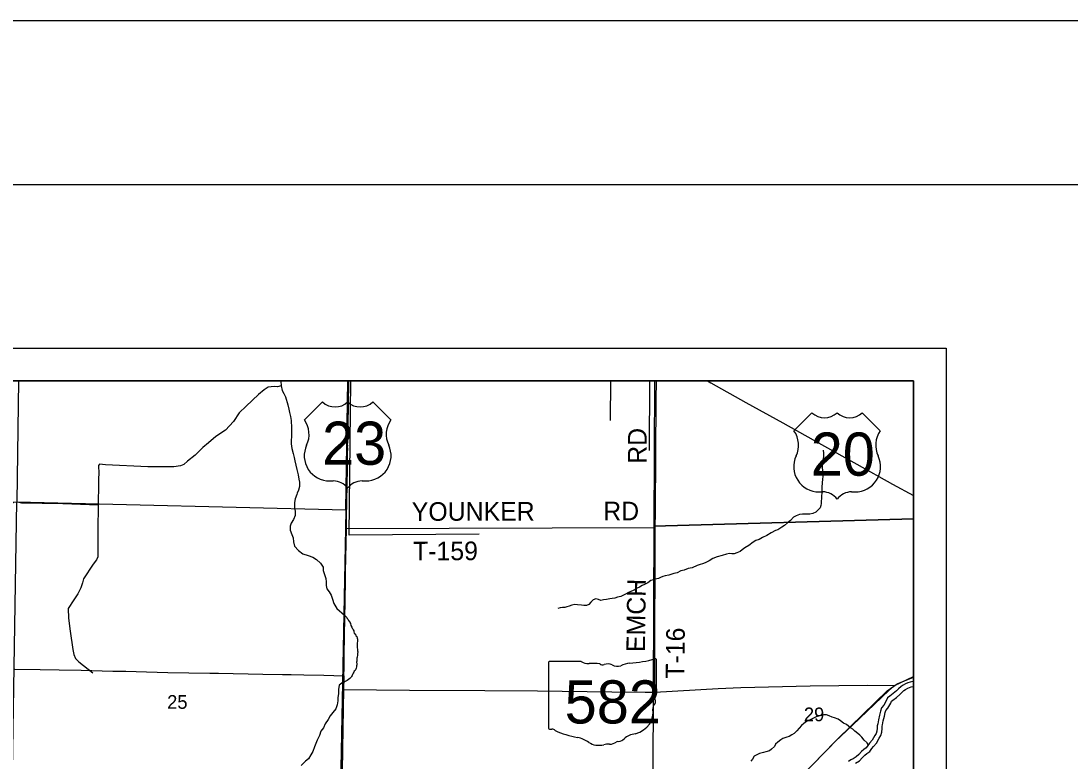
# Model space of a CAD drawing. Extents: x 0 to 34, y 0 to 22.
# Drawn here: x 6.172 to 9.379, y 19.739 to 22 of the extents above; entities that cross this region are included whole.
import ezdxf

# ---------------------------------------------------------------- set-up
doc = ezdxf.new("R2010")
doc.units = 0
for name, color, linetype in [('Default', 7, 'Continuous'), ('GM_X_Major_River', 7, 'Continuous'), ('GM_X_Minor_River', 7, 'Continuous'), ('GM_X_Rail_Line', 7, 'Continuous'), ('GM_X_Section', 7, 'Continuous'), ('GM_X_Section_Text', 7, 'Continuous'), ('GM_X_State_Location', 7, 'Continuous'), ('GM_X_State_Route', 7, 'Continuous'), ('GM_X_State_Shield', 7, 'Continuous'), ('GM_X_Township_Road', 7, 'Continuous'), ('GM_X_Township_Road_Text', 7, 'Continuous'), ('GM_X_US_Location', 7, 'Continuous'), ('GM_X_US_Route', 7, 'Continuous'), ('GM_X_US_Shield', 7, 'Continuous'), ('SH_Border', 7, 'Continuous'), ('SH_Cut_Line', 7, 'Continuous'), ('SH_Data', 7, 'Continuous')]:
    doc.layers.add(name, color=color, linetype=linetype)

msp = doc.modelspace()

# ---------------------------------------------------------------- linework, layer by layer
at = {"layer": 'Default'}
for points in [[(7.1537, 19.7074), (7.1558, 19.838), (7.1582, 19.9576), (7.1584, 19.9701), (7.1585, 19.983), (7.1586, 19.9996), (7.1589, 20.0234), (7.1593, 20.0575), (7.1605, 20.1258), (7.1613, 20.1709), (7.1624, 20.2315), (7.1626, 20.2502), (7.1628, 20.2688), (7.1637, 20.317), (7.1651, 20.4024), (7.1662, 20.449), (7.1662, 20.4497), (7.1667, 20.4801), (7.1675, 20.5329), (7.1683, 20.5811), (7.1691, 20.6324), (7.1697, 20.665), (7.1697, 20.679), (7.1699, 20.6945), (7.1698, 20.6976), (7.1699, 20.7023), (7.1698, 20.7054), (7.1699, 20.7132), (7.1711, 20.766), (7.1724, 20.8281), (7.1733, 20.8949), (7.1734, 20.9), (3.1549, 20.9)], [(8.9, 16.9874), (8.9, 20.9), (7.1734, 20.9), (7.1733, 20.8949), (7.1724, 20.8281), (7.1711, 20.766), (7.1699, 20.7132), (7.1698, 20.7054), (7.1699, 20.7023), (7.1698, 20.6976), (7.1699, 20.6945), (7.1697, 20.679), (7.1697, 20.665), (7.1691, 20.6324), (7.1683, 20.5811), (7.1675, 20.5329), (7.1667, 20.4801), (7.1662, 20.4497), (7.1662, 20.449), (7.1651, 20.4024), (7.1637, 20.317), (7.1628, 20.2688), (7.1626, 20.2502), (7.1624, 20.2315), (7.1613, 20.1709), (7.1605, 20.1258), (7.1593, 20.0575), (7.1589, 20.0234), (7.1586, 19.9996), (7.1585, 19.983), (7.1584, 19.9701), (7.1582, 19.9576), (7.1558, 19.838), (7.1537, 19.7074)]]:
    msp.add_lwpolyline(points, dxfattribs=at)
for points in [[(7.1717, 20.9), (6.1646, 20.9), (6.1602, 20.5302), (7.1654, 20.5062)], [(8.9, 20.4788), (8.9, 20.9), (8.1091, 20.9), (8.1063, 20.4559)], [(8.9, 19.4792), (8.9, 20.4788), (8.1063, 20.4559), (8.1023, 19.4482)]]:
    msp.add_lwpolyline(points, close=True, dxfattribs=at)
at = {"layer": 'GM_X_Major_River'}
for points in [[(8.9, 19.9817), (8.8977, 19.9814), (8.8901, 19.9798), (8.8829, 19.9779), (8.8753, 19.974), (8.8685, 19.9702), (8.8621, 19.9664), (8.8541, 19.9591), (8.8481, 19.9526), (8.8386, 19.945), (8.8277, 19.9366), (8.8212, 19.9312), (8.8171, 19.9225), (8.8092, 19.9088), (8.8024, 19.9008), (8.7994, 19.8913), (8.7964, 19.8787), (8.793, 19.8647), (8.7908, 19.8525), (8.7893, 19.846), (8.7897, 19.8384), (8.7882, 19.8297), (8.7863, 19.8225), (8.7822, 19.816), (8.7743, 19.8023), (8.766, 19.7928), (8.7603, 19.7855), (8.7558, 19.7787), (8.7486, 19.7733), (8.741, 19.7672), (8.7327, 19.7584), (8.7255, 19.7512), (8.7157, 19.7454), (8.7092, 19.742), (8.7013, 19.7366)], [(8.7231, 19.7322), (8.7349, 19.7391), (8.7436, 19.7479), (8.7513, 19.756), (8.7579, 19.7613), (8.767, 19.7681), (8.7726, 19.7767), (8.7777, 19.7831), (8.7867, 19.7934), (8.7952, 19.8081), (8.8004, 19.8163), (8.8031, 19.8265), (8.8049, 19.8376), (8.8045, 19.8447), (8.8056, 19.8494), (8.8079, 19.8615), (8.8111, 19.8752), (8.814, 19.8872), (8.8159, 19.8933), (8.8216, 19.9), (8.8305, 19.9154), (8.8335, 19.9217), (8.8371, 19.9247), (8.848, 19.9331), (8.8584, 19.9415), (8.8648, 19.9483), (8.8712, 19.9541), (8.8761, 19.9571), (8.8825, 19.9607), (8.8884, 19.9636), (8.8936, 19.965), (8.9, 19.9664)]]:
    msp.add_lwpolyline(points, dxfattribs=at)
at = {"layer": 'GM_X_Minor_River'}
for p, q in [((7.1759, 20.4285), (7.1802, 20.9)), ((7.9745, 20.9), (7.9729, 20.7792)), ((8.093, 20.9), (8.0923, 20.6874)), ((7.1758, 20.4288), (7.1759, 20.4288)), ((7.5724, 20.432), (7.1759, 20.4285))]:
    msp.add_line(p, q, dxfattribs=at)
for points in [[(6.9678, 20.8853), (6.9564, 20.8821), (6.9458, 20.8828), (6.9276, 20.8805), (6.9153, 20.8729), (6.8983, 20.8581), (6.8603, 20.8233), (6.8389, 20.8022), (6.822, 20.7761), (6.7979, 20.7497), (6.7682, 20.7307), (6.7458, 20.7108), (6.7284, 20.6964), (6.7051, 20.6734), (6.6819, 20.655), (6.6699, 20.6447), (6.6596, 20.6407), (6.6394, 20.6374), (6.5599, 20.6378), (6.4313, 20.644), (6.4128, 20.646), (6.4096, 20.6415), (6.4102, 20.6168), (6.4098, 20.602), (6.4091, 20.5872), (6.4085, 20.5208), (6.4078, 20.4446), (6.4076, 20.374), (6.4076, 20.3626), (6.4029, 20.3529), (6.3934, 20.3398), (6.3632, 20.295), (6.3602, 20.2829), (6.3553, 20.2682), (6.3461, 20.2495), (6.3336, 20.2308), (6.317, 20.205), (6.3174, 20.175), (6.3225, 20.1355), (6.3313, 20.0795), (6.3336, 20.0642), (6.3386, 20.0523), (6.3493, 20.0414), (6.3924, 20.0085)], [(6.9666, 20.9), (6.9667, 20.8989), (6.9678, 20.8853), (6.9709, 20.8711), (6.9756, 20.8615), (6.9806, 20.8515), (6.9876, 20.8267), (6.9911, 20.8137), (6.9931, 20.8031), (6.9958, 20.7912), (6.9978, 20.779), (6.9995, 20.757), (6.9995, 20.7426), (6.9988, 20.7289), (6.9982, 20.7191), (6.9986, 20.7073), (7.0006, 20.6932), (7.004, 20.6783), (7.0078, 20.6657), (7.0095, 20.6562), (7.0129, 20.6424), (7.016, 20.6298), (7.0198, 20.613), (7.0221, 20.6001), (7.0238, 20.5905), (7.0238, 20.5776), (7.0205, 20.5667), (7.0161, 20.557)], [(8.6241, 20.6883), (8.6253, 20.6788), (8.6253, 20.6719), (8.6242, 20.6594), (8.6219, 20.6488), (8.6216, 20.6408), (8.6212, 20.6343), (8.622, 20.6271), (8.6228, 20.6195), (8.6229, 20.6093), (8.6225, 20.599), (8.6214, 20.5899), (8.6203, 20.5747), (8.62, 20.5656), (8.6196, 20.5561), (8.6193, 20.5497), (8.6189, 20.5421), (8.6182, 20.5318), (8.6182, 20.5254), (8.6175, 20.5189), (8.6149, 20.5121), (8.6081, 20.5052), (8.6013, 20.4991), (8.5929, 20.4945), (8.5838, 20.4929), (8.569, 20.4925), (8.5607, 20.4924), (8.552, 20.492), (8.5414, 20.4881), (8.5334, 20.4836), (8.5243, 20.4736), (8.5156, 20.4668), (8.5058, 20.458), (8.4978, 20.453), (8.4854, 20.4453), (8.4782, 20.443), (8.4653, 20.4361), (8.4516, 20.4277), (8.4388, 20.4212), (8.4282, 20.415), (8.4183, 20.4123), (8.4107, 20.4077), (8.3967, 20.3974), (8.3843, 20.3901), (8.3767, 20.3836), (8.3703, 20.3791), (8.3608, 20.3748), (8.3524, 20.3718), (8.3449, 20.3721), (8.3376, 20.3724), (8.3289, 20.3705), (8.3153, 20.3662), (8.2997, 20.3624), (8.2865, 20.3574), (8.2755, 20.3505), (8.2634, 20.3443), (8.2558, 20.3409), (8.2482, 20.3386), (8.2395, 20.3355), (8.224, 20.3289), (8.2118, 20.3266), (8.199, 20.322), (8.1887, 20.3193), (8.1777, 20.3139), (8.1679, 20.3112), (8.1588, 20.3089), (8.152, 20.3069), (8.1417, 20.3046), (8.1338, 20.3023), (8.1273, 20.2996), (8.1209, 20.2965), (8.111, 20.2938), (8.1042, 20.2919), (8.097, 20.2899), (8.0887, 20.2827), (8.0777, 20.2784), (8.0713, 20.2746), (8.0633, 20.27), (8.0561, 20.2666), (8.0466, 20.2604), (8.0387, 20.2577), (8.0296, 20.2531), (8.0205, 20.2482), (8.0141, 20.2455), (8.0054, 20.2412), (7.9959, 20.2389), (7.9875, 20.2362), (7.9796, 20.2354), (7.9724, 20.2346), (7.9621, 20.2323), (7.9527, 20.2311), (7.9447, 20.2292), (7.9379, 20.2325), (7.9291, 20.2344), (7.9208, 20.2309), (7.9144, 20.2237), (7.9076, 20.2172), (7.9004, 20.2137), (7.8928, 20.2133), (7.8856, 20.2148), (7.8734, 20.2155)], [(7.0161, 20.557), (7.0153, 20.5528), (7.0108, 20.5396), (7.0082, 20.5287), (7.0086, 20.5139), (7.0109, 20.5009), (7.0103, 20.4892), (7.005, 20.4768), (6.9987, 20.4655), (6.9954, 20.4557), (6.9951, 20.4436), (7.0001, 20.4306), (7.0044, 20.421), (7.0056, 20.4084), (7.0083, 20.3951), (7.0205, 20.3823), (7.0339, 20.3721), (7.05, 20.3664), (7.0643, 20.3611), (7.0758, 20.3544)], [(6.4085, 20.5208), (6.3, 20.5246), (6.1739, 20.5261), (6.1619, 20.5299), (6.1493, 20.5283), (6.142, 20.5235), (6.1391, 20.5122), (6.1372, 20.3437)], [(7.0758, 20.3544), (7.0877, 20.3427), (7.0957, 20.3307), (7.0962, 20.3209), (7.0997, 20.309), (7.1043, 20.2964), (7.1048, 20.2857), (7.1053, 20.2747), (7.1077, 20.2652), (7.1139, 20.2552), (7.1201, 20.2455), (7.1247, 20.2329), (7.1282, 20.2199), (7.1377, 20.2049), (7.1613, 20.1842)], [(7.8734, 20.2155), (7.8654, 20.2166), (7.8556, 20.2146), (7.8476, 20.2116), (7.8412, 20.2093), (7.8347, 20.2073), (7.8279, 20.2073), (7.8199, 20.2069), (7.8135, 20.2046)], [(7.1613, 20.1842), (7.1664, 20.1793), (7.1679, 20.1766), (7.1698, 20.1736), (7.172, 20.1709), (7.1735, 20.1682), (7.1761, 20.1655), (7.1779, 20.1621), (7.1794, 20.159), (7.1804, 20.1529), (7.1838, 20.1476), (7.1849, 20.1449), (7.1867, 20.1422), (7.1878, 20.1392), (7.1893, 20.1361), (7.1896, 20.1331), (7.1911, 20.1289), (7.1944, 20.1258), (7.1962, 20.1212), (7.1989, 20.1186), (7.1999, 20.1144), (7.2006, 20.1109), (7.2005, 20.1037), (7.2001, 20.1), (7.2, 20.092), (7.2003, 20.0893), (7.2002, 20.0855), (7.2013, 20.0798), (7.2012, 20.0749), (7.2016, 20.0719), (7.2011, 20.0673), (7.201, 20.0624), (7.2002, 20.0563), (7.1994, 20.0529), (7.1989, 20.0465), (7.1985, 20.0434), (7.1984, 20.0408), (7.1991, 20.0359), (7.1991, 20.0324), (7.1979, 20.029), (7.1975, 20.026), (7.197, 20.0222), (7.1958, 20.0192), (7.1935, 20.0154), (7.1912, 20.0128), (7.1893, 20.0098), (7.1881, 20.0068), (7.1858, 20.003), (7.1846, 20), (7.1831, 19.9972), (7.1821, 19.9951)], [(7.1575, 19.979), (7.1449, 19.97), (7.1432, 19.9569), (7.1425, 19.9437), (7.1411, 19.9327), (7.1409, 19.9228), (7.1387, 19.91), (7.1346, 19.8979), (7.1256, 19.8864), (7.1174, 19.8767), (7.1114, 19.8651), (7.1024, 19.852), (7.0968, 19.8404), (7.0893, 19.8296), (7.0852, 19.8164), (7.0777, 19.8025), (7.074, 19.792), (7.07, 19.7815), (7.0647, 19.7676), (7.058, 19.7579), (7.0513, 19.7451), (7.0416, 19.7385), (7.0284, 19.7252)], [(7.1821, 19.9951), (7.1778, 19.991), (7.1689, 19.9848), (7.1612, 19.9804), (7.1575, 19.979)], [(8.7614, 19.7869), (8.7588, 19.7943), (8.7496, 19.8022), (8.742, 19.8109), (8.7363, 19.8173), (8.7298, 19.8226), (8.7214, 19.8294), (8.715, 19.8358), (8.7081, 19.8399), (8.6952, 19.8501), (8.6864, 19.8538), (8.6769, 19.8618), (8.6697, 19.8667), (8.659, 19.8708), (8.6518, 19.8723), (8.6427, 19.8768), (8.634, 19.8794), (8.6264, 19.8793), (8.6192, 19.8774), (8.6124, 19.8762), (8.6025, 19.8731), (8.5927, 19.8685), (8.582, 19.8635), (8.5737, 19.8589), (8.565, 19.8536), (8.5578, 19.8471), (8.551, 19.8391), (8.5438, 19.8311), (8.5351, 19.8227), (8.528, 19.8185), (8.52, 19.8139), (8.5132, 19.8112), (8.5011, 19.8073), (8.4946, 19.8035), (8.4855, 19.7966), (8.4787, 19.7905), (8.4753, 19.7833), (8.4663, 19.7749), (8.4598, 19.7695), (8.4492, 19.7664), (8.442, 19.7641), (8.4295, 19.7614), (8.4129, 19.753), (8.4083, 19.7446), (8.4027, 19.7381)]]:
    msp.add_lwpolyline(points, dxfattribs=at)
at = {"layer": 'GM_X_Rail_Line'}
msp.add_lwpolyline([(7.1295, 18.535), (7.5214, 18.7256), (7.5415, 18.727), (7.7361, 18.8905), (7.8156, 18.9525), (8.1721, 19.3059), (8.3177, 19.4462), (8.6699, 19.8071), (8.8197, 19.9527), (8.8503, 19.9748), (8.9, 19.9949)], dxfattribs=at)
at = {"layer": 'GM_X_Section'}
msp.add_lwpolyline([(7.1654, 20.5062), (7.1646, 20.4494), (7.146, 19.507), (6.1433, 19.5215), (6.1602, 20.5302)], close=True, dxfattribs=at)
at = {"layer": 'GM_X_State_Route'}
for points in [[(6.1537, 20.0192), (6.2312, 20.0182), (6.289, 20.0171), (6.3561, 20.0157), (6.4537, 20.0135), (6.4928, 20.013), (6.5556, 20.0108), (6.6213, 20.0092), (6.7493, 20.0071), (6.7766, 20.0065), (6.9114, 20.0043), (6.972, 20.0029), (6.9981, 20.0026), (7.0373, 20.0017), (7.0982, 20.0005), (7.1588, 19.9991)], [(7.1275, 18.3685), (7.1654, 18.4136), (7.3608, 18.5932), (7.4758, 18.6969), (7.6618, 18.8326), (7.7258, 18.8796), (7.8269, 18.9622), (7.9458, 19.0794), (8.0941, 19.2274), (8.2454, 19.3754), (8.3174, 19.4447), (8.6611, 19.7985), (8.7135, 19.8476), (8.8036, 19.9332), (8.8247, 19.9539), (8.842, 19.9695), (8.8812, 19.988), (8.9, 19.9963)], [(7.1588, 19.9991), (7.1587, 19.9825), (7.1586, 19.9696), (7.1584, 19.957)], [(7.1584, 19.957), (7.3598, 19.9553), (7.5901, 19.954), (7.751, 19.9528), (7.9784, 19.9503), (8.0804, 19.9489), (8.1099, 19.9492), (8.3034, 19.9597), (8.3727, 19.9633), (8.5846, 19.9687), (8.7596, 19.9706), (8.842, 19.9695)]]:
    msp.add_lwpolyline(points, dxfattribs=at)
at = {"layer": 'GM_X_State_Shield'}
for p, q in [((7.7851, 20.0392), (7.7851, 19.839)), ((7.8849, 20.0426), (7.7884, 20.0426)), ((8.1147, 19.9429), (8.1147, 20.0476)), ((8.1147, 19.9429), (8.1147, 19.9429))]:
    msp.add_line(p, q, dxfattribs=at)
for centre, major_axis, start_param, end_param in [((7.7889, 20.0396), (0.00382, 0), 1.712693, 3.28349), ((7.9079, 20.0658), (0.037, 0), 4.042523, 4.731795), ((7.9973, 20.3154), (0.3495, 0), 4.814394, 5.042369), ((8.1111, 20.048), (0.00367, 0), 6.141152, 7.989035), ((7.9202, 19.9303), (0.133, 0), 1.404758, 1.657858), ((7.9503, 20.0406), (0.0107, 0), 3.836095, 5.185415), ((7.966, 20.0175), (0.0222, 0), 0.950623, 2.079405), ((7.9947, 20.0492), (0.0267, 0), 4.081561, 5.145723), ((8.0419, 19.9815), (0.0703, 0), 1.699011, 2.107814), ((8.1108, 19.9425), (0.00393, 0), 5.05454, 6.418171), ((8.1279, 19.8991), (0.0248, 0), 2.387724, 3.262537), ((8.1139, 19.9352), (0.00568, 0), 1.883978, 3.671073), ((8.0777, 19.922), (0.0341, 0), 5.934695, 6.695948), ((8.0169, 19.8858), (0.0874, 0), 5.101752, 6.440018), ((7.7889, 19.8386), (0.00385, 0), 3.00124, 4.508301), ((7.7895, 19.8591), (0.0294, 0), 4.665946, 4.897461), ((7.7955, 19.8275), (0.0106, 0), 0.519207, 1.627899), ((7.9294, 20.0073), (0.2524, 0), 4.195997, 4.488961), ((8.0538, 19.7829), (0.0479, 0), 1.647645, 2.488434), ((7.8541, 19.7491), (0.079, 0), 0.823519, 1.323587), ((7.9395, 19.8265), (0.0501, 0), 4.026481, 4.996735), ((7.9685, 19.7573), (0.0412, 0), 1.495662, 1.94098), ((7.9721, 19.8115), (0.0267, 0), 4.691044, 5.507374), ((7.9963, 19.7921), (0.00752, 0), 1.147584, 2.315152), ((7.9931, 19.8197), (0.0282, 0), 4.937069, 5.64225)]:
    msp.add_ellipse(centre, major_axis=major_axis, ratio=0.8, start_param=start_param, end_param=end_param, dxfattribs=at)
at = {"layer": 'GM_X_Township_Road'}
msp.add_line((7.1664, 20.4491), (8.111, 20.4526), dxfattribs=at)
msp.add_lwpolyline([(8.1099, 19.9492), (8.1099, 20.1373), (8.1104, 20.3284), (8.111, 20.4526), (8.1115, 20.4993), (8.113, 20.6764), (8.114, 20.8425), (8.1146, 20.9)], dxfattribs=at)
at = {"layer": 'GM_X_US_Route'}
for points in [[(7.1588, 19.9991), (7.1591, 20.0229), (7.1595, 20.0569), (7.1608, 20.1253), (7.1615, 20.1703), (7.1627, 20.2309), (7.1628, 20.2496), (7.163, 20.2682), (7.1639, 20.3164), (7.1654, 20.4019), (7.1664, 20.4485), (7.1664, 20.4491), (7.167, 20.4795), (7.1678, 20.5324), (7.1685, 20.5805), (7.1693, 20.6318), (7.17, 20.6644), (7.1699, 20.6784), (7.1701, 20.694), (7.17, 20.6971), (7.1701, 20.7017), (7.17, 20.7048), (7.1701, 20.7126), (7.1713, 20.7654), (7.1726, 20.8276), (7.1735, 20.8944), (7.1736, 20.9)], [(8.2711, 20.9), (8.2807, 20.8946), (8.388, 20.8346), (8.5008, 20.7717), (8.6192, 20.7059), (8.7272, 20.6456), (8.8364, 20.5849), (8.9, 20.5495)], [(7.1584, 19.957), (7.1586, 19.9696), (7.1587, 19.9825), (7.1588, 19.9991)], [(7.1539, 19.7069), (7.156, 19.8374), (7.1584, 19.957)]]:
    msp.add_lwpolyline(points, dxfattribs=at)
at = {"layer": 'GM_X_US_Shield'}
for p, q in [((7.094, 20.836), (7.0391, 20.7811)), ((7.3027, 20.7811), (7.2478, 20.836)), ((8.59, 20.8028), (8.535, 20.7478)), ((8.7987, 20.7478), (8.7438, 20.8028)), ((7.116, 20.5943), (7.127, 20.5943)), ((7.2148, 20.5943), (7.2258, 20.5943)), ((8.6119, 20.5611), (8.6229, 20.5611)), ((8.7108, 20.5611), (8.7218, 20.5611))]:
    msp.add_line(p, q, dxfattribs=at)
for centre, radius, start, end in [((7.1324, 20.8753), 0.0549, 225.573, 314.427), ((7.2093, 20.8753), 0.0549, 225.573, 314.427), ((6.9761, 20.737), 0.0769, 334.5471, 35.0009), ((7.3657, 20.737), 0.0769, 144.9991, 205.4529), ((8.6284, 20.842), 0.0549, 225.573, 314.427), ((8.7053, 20.842), 0.0549, 225.573, 314.427), ((8.472, 20.7037), 0.0769, 334.5471, 35.0009), ((8.8617, 20.7037), 0.0769, 144.9991, 205.4529), ((7.1151, 20.6712), 0.0769, 154.8319, 270.6383), ((7.2267, 20.6712), 0.0769, 269.3617, 25.1681), ((8.6111, 20.638), 0.0769, 154.8319, 270.6383), ((8.7226, 20.638), 0.0769, 269.3617, 25.1681), ((7.127, 20.5394), 0.0549, 36.8699, 90), ((7.2148, 20.5394), 0.0549, 90, 143.1301), ((8.6229, 20.5061), 0.0549, 36.8699, 90), ((8.7108, 20.5061), 0.0549, 90, 143.1301)]:
    msp.add_arc(centre, radius, start, end, dxfattribs=at)
at = {"layer": 'SH_Border'}
msp.add_lwpolyline([(1.5, 21.5), (33.5, 21.5), (33.5, 0.5), (1.5, 0.5)], close=True, dxfattribs=at)
at = {"layer": 'SH_Cut_Line'}
msp.add_lwpolyline([(0, 0), (34, 0), (34, 22), (0, 22)], close=True, dxfattribs=at)
for points in [[(7.1537, 19.7074), (7.1558, 19.838), (7.1582, 19.9576), (7.1584, 19.9701), (7.1585, 19.983), (7.1586, 19.9996), (7.1589, 20.0234), (7.1593, 20.0575), (7.1605, 20.1258), (7.1613, 20.1709), (7.1624, 20.2315), (7.1626, 20.2502), (7.1628, 20.2688), (7.1637, 20.317), (7.1651, 20.4024), (7.1662, 20.449), (7.1662, 20.4497), (7.1667, 20.4801), (7.1675, 20.5329), (7.1683, 20.5811), (7.1691, 20.6324), (7.1697, 20.665), (7.1697, 20.679), (7.1699, 20.6945), (7.1698, 20.6976), (7.1699, 20.7023), (7.1698, 20.7054), (7.1699, 20.7132), (7.1711, 20.766), (7.1724, 20.8281), (7.1733, 20.8949), (7.1734, 20.9), (2.1, 20.9)], [(8.9, 14.1), (8.9, 20.9), (7.1734, 20.9), (7.1733, 20.8949), (7.1724, 20.8281), (7.1711, 20.766), (7.1699, 20.7132), (7.1698, 20.7054), (7.1699, 20.7023), (7.1698, 20.6976), (7.1699, 20.6945), (7.1697, 20.679), (7.1697, 20.665), (7.1691, 20.6324), (7.1683, 20.5811), (7.1675, 20.5329), (7.1667, 20.4801), (7.1662, 20.4497), (7.1662, 20.449), (7.1651, 20.4024), (7.1637, 20.317), (7.1628, 20.2688), (7.1626, 20.2502), (7.1624, 20.2315), (7.1613, 20.1709), (7.1605, 20.1258), (7.1593, 20.0575), (7.1589, 20.0234), (7.1586, 19.9996), (7.1585, 19.983), (7.1584, 19.9701), (7.1582, 19.9576), (7.1558, 19.838), (7.1537, 19.7074)]]:
    msp.add_lwpolyline(points, dxfattribs=at)
at = {"layer": 'SH_Data'}
for p, q in [((2, 21), (9, 21)), ((9, 21), (9, 14)), ((2.1, 20.9), (8.9, 20.9)), ((8.9, 20.9), (8.9, 14.1))]:
    msp.add_line(p, q, dxfattribs=at)

# ---------------------------------------------------------------- texts
at = {"layer": 'GM_X_Section_Text'}
for s, p in [('25', (6.6192, 19.898)), ('29', (8.5652, 19.8601))]:
    msp.add_text(s, height=0.04186, rotation=0, dxfattribs=at).set_placement(p)
at = {"layer": 'GM_X_State_Location'}
msp.add_text('582', height=0.000189, rotation=0, dxfattribs=at).set_placement((7.8794, 19.912))
for s in ['s', 'r']:
    msp.add_text(s, height=0.000189, dxfattribs=at).set_placement((7.9462, 19.9258))
at = {"layer": 'GM_X_State_Shield'}
msp.add_text('582', height=0.13184, dxfattribs=at).set_placement((7.8341, 19.8532))
at = {"layer": 'GM_X_Township_Road_Text'}
for s, rotation, p in [('RD', 90, (8.0845, 20.6467)), ('YOUNKER', 0.1412, (7.3668, 20.4724)), ('RD', 0, (7.9519, 20.4741)), ('T-159', 0.2818, (7.3707, 20.3515)), ('EMCH', 89.2867, (8.0795, 20.0712)), ('T-16', 89.2924, (8.1996, 19.9897))]:
    msp.add_text(s, height=0.05682, rotation=rotation, dxfattribs=at).set_placement(p)
at = {"layer": 'GM_X_US_Location'}
for s, p in [('0', (7.1708, 20.7086)), ('/', (7.1708, 20.7086)), ('0', (8.6668, 20.6754)), ('/', (8.6668, 20.6754))]:
    msp.add_text(s, height=0.000189, dxfattribs=at).set_placement(p)
for s, p in [('23', (7.1317, 20.6694)), ('20', (8.6277, 20.6362))]:
    msp.add_text(s, height=0.000189, rotation=0, dxfattribs=at).set_placement(p)
at = {"layer": 'GM_X_US_Shield'}
for s, p in [('23', (7.0926, 20.6438)), ('20', (8.586, 20.6105))]:
    msp.add_text(s, height=0.13184, dxfattribs=at).set_placement(p)

doc.saveas('drawing.dxf')
